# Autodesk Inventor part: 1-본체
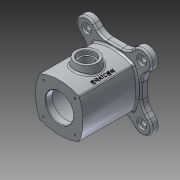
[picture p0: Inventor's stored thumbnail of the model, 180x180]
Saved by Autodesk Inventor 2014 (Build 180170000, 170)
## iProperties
Created: 2016-05
Part Number: 1-본체
Material: 알루미늄 6061
Document SubType Name: Modeling
Designer: G.C.Oh
Density: 2.71 g/cm^3
Appearance: 알루미늄 - 평지
Mass: 1103.61 g
Surface Area: 865.116 cm^2
Volume: 407.235 cm^3
Author: G.C.Oh
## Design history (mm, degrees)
sketch "스케치1"
  geometry: L1 (43, 43)-(-43, 43); L2 (-43, 43)-(-43, -43); L3 (-43, -43)-(43, -43); L4 (43, -43)-(43, 43); L5 (43, 43)-(-43, -43); L6 (-43, 43)-(43, -43); A1 r 50 centre (0, 0) between (35.355, -35.355) and (35.355, 35.355); A2 r 85.579 centre (-42.579, 0) between (35.355, -35.355) and (35.355, 35.355); A3 r 90.136 centre (47.557, 0) between (-35.355, 35.355) and (-35.355, -35.355); A4 r 85.579 centre (0, -42.579) between (35.355, 35.355) and (-35.355, 35.355); A5 r 90.136 centre (0, 47.557) between (-35.355, -35.355) and (35.355, -35.355); 1 further point
  constraints: 14 point on circle, 12 end point, 5 centre point, 4 point on line, 2 midpoint, 2 parallel, 2 tangent, 1 coincident, 1 horizontal, 1 perpendicular
  dimensions: "d6" = 86 distance of L2.end L3.end; "d7" = 86 distance of L1.end L2.end; "d8" = 100 diameter of A1
extrude "돌출1" new body sketch "스케치1" distance "d9" = 55; taper "d10" = 0 deg
sketch "스케치4"
  geometry: 1 further point
hole "구멍5" sketch "스케치4" at (0, 0) diameter "d68" = 50; stored, may be unused: countersink angle "d72" = 90 deg, drill point angle "d74" = 118 deg; dims "d69" = 6, "d70" = 70, "d71" = 43, "d73" = 8
fillet "모깎기3" dims "d75" = 3
node "작업 평면2"
sketch "스케치2"
  geometry: L1 (35.355, -55)-(-35.355, -55) reference; C1 r 20 at (0, -6); 2 further points
  constraints: 1 centre point, 1 coincident, 1 midpoint, 1 vertical alignment
  dimensions: "d124" = 49 distance from line of point (0, -6) L1; "d125" = 40 diameter of C1
extrude "돌출2" join sketch "스케치2" stored distance "d13" = 110; taper "d14" = 10 deg
sketch "스케치3"
  geometry: L1 (49, 49)-(-49, 49); L2 (-49, 49)-(-49, -49); L3 (-49, -49)-(49, -49); L4 (49, -49)-(49, 49); L5 (49, 49)-(-49, -49); L6 (-49, 49)-(49, -49); L7 (36.77, -62.225)-(23.544, -49); L8 (62.225, -36.77)-(49, -23.544); C1 r 18 at (-49.497, -49.497); C2 r 18 at (49.497, 49.497); C3 r 18 at (-49.497, 49.497); A1 r 70 centre (0, 0) between (-49.497, -49.497) and (49.497, -49.497); A2 r 18 centre (49.497, -49.497) between (35.239, -60.483) and (60.483, -35.239); 1 further point
  constraints: 16 end point, 10 point on circle, 6 point on line, 5 centre point, 4 parallel, 2 midpoint, 2 tangent, 1 coincident, 1 horizontal, 1 perpendicular
  dimensions: "d16" = 70 radius of A1; "d17" = 90 deg angle of L5 L6; "d18" = 36 diameter of C1; "d19" = 36 diameter of A2; "d20" = 36 diameter of C2; "d21" = 36 diameter of C3; "d22" = 98 distance of L2.end L3.end
extrude "돌출3" join sketch "스케치3" distance "d23" = 12; taper "d24" = 0 deg
extrude "돌출4" join sketch "스케치3" distance "d25" = 12; taper "d26" = 0 deg
fillet "모깎기1" dims "d30" = 25
hole "구멍1" diameter "d33" = 10; stored, may be unused: countersink angle "d37" = 90 deg, drill point angle "d39" = 118 deg; dims "d31" = 10, "d32" = 10, "d34" = 6, "d35" = 18, "d36" = 4, "d38" = 8
hole "구멍2" diameter "d42" = 10; stored, may be unused: countersink angle "d46" = 90 deg, drill point angle "d48" = 118 deg; dims "d40" = 10, "d41" = 10, "d43" = 6, "d44" = 18, "d45" = 4, "d47" = 8
hole "구멍3" diameter "d51" = 10; stored, may be unused: countersink angle "d55" = 90 deg, drill point angle "d57" = 118 deg; dims "d49" = 10, "d50" = 10, "d52" = 6, "d53" = 18, "d54" = 4, "d56" = 8
hole "구멍4" diameter "d60" = 10; stored, may be unused: countersink angle "d64" = 90 deg, drill point angle "d66" = 118 deg; dims "d58" = 10, "d59" = 10, "d61" = 6, "d62" = 18, "d63" = 4, "d65" = 8
sketch "스케치5"
  geometry: 1 further point
hole "구멍6" sketch "스케치5" at (0, 0) diameter "d76" = 50; stored, may be unused: countersink angle "d80" = 90 deg, drill point angle "d82" = 118 deg; dims "d77" = 6, "d78" = 70, "d79" = 43, "d81" = 12
hole "구멍7" diameter "d85" = 25; stored, may be unused: countersink angle "d89" = 90 deg, drill point angle "d91" = 118 deg; dims "d83" = 10, "d84" = 10, "d86" = 6, "d87" = 30, "d88" = 8, "d90" = 12
chamfer "모따기1" distance "d92" = 1; stored, may be unused: second distance "d93" = 2, angle "d94" = 45 deg
fillet "모깎기4" dims "d95" = 3
fillet "모깎기5" dims "d96" = 3
fillet "모깎기6" dims "d97" = 3
fillet "모깎기7" dims "d98" = 3
sketch "스케치6" dims "d99" = 40
  geometry: L1 (0.01, 42.579)-(-28.268, 70.87); L2 (0.032, 137.075)-(-0.012, -51.918) reference; 1 further point
  constraints: 2 end point, 1 coincident, 3 other
  dimensions: "d100" = 45 deg angle of L2 L1
hole "구멍8" sketch "스케치6" at (-28.268, 70.87) diameter "d101" = 3.242; stored, may be unused: countersink angle "d105" = 90 deg, drill point angle "d107" = 118 deg; dims "d102" = 7, "d103" = 30, "d104" = 8, "d106" = 10
sketch "스케치7" dims "d112" = 40
  geometry: L1 (0, 94.496)-(0, -94.496) reference; L2 (0, 0)-(28.284, -28.284); 1 further point
  constraints: 2 end point, 1 coincident, 3 other
  dimensions: "d113" = 45 deg angle of L1 L2
hole "구멍9" sketch "스케치7" at (28.284, -28.284) diameter "d114" = 3.242; stored, may be unused: countersink angle "d118" = 90 deg, drill point angle "d120" = 118 deg; dims "d115" = 7, "d116" = 30, "d117" = 8, "d119" = 10
node "작업 평면5"
sketch "스케치11"
  geometry: L1 (34.248, -55)-(-34.285, -55) reference; C1 r 16 at (0, -6) reference; 2 further points
  constraints: 1 other
  dimensions: "d130" = 29 distance of point (29, -6) C1.centre; "d131" = 49 distance from line of point (29, -6) L1
feature "엠보싱2" sketch "스케치11" dims "d6" = 86, "d7" = 86, "d8" = 100, "d16" = 70, "d17" = 90 deg, "d18" = 36, "d19" = 36, "d20" = 36, "d21" = 36, "d22" = 98, "d132" = 0.5, "d133" = 0
node "솔리드1"
mirror "대칭1"
pattern_circular "원형 패턴1" dims angle "d28" = 360 deg
pattern_circular "원형 패턴2" dims angle "d109" = 360 deg
pattern_circular "원형 패턴3" dims angle "d122" = 360 deg
other parameters: "d11" = 55
